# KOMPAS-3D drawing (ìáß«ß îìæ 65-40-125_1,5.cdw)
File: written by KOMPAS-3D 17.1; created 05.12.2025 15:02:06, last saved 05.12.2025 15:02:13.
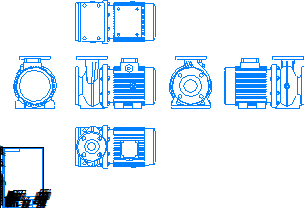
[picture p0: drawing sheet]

Sheet 1: A4, portrait

Title block, sheet 1: name: Насос МНС / 65-40-125_1,5; material: Сталь 10  ГОСТ 1050-88; mass: 75,87; sheets: 1; sheet format: A4

Views: Проекционный вид 2, Проекционный вид 3, Проекционный вид 4, Проекционный вид 5, Проекционный вид 6
Referenced files in \\adlc.lan\data\АДЛ_ПКД\3D-модели\ADL production\Насосы ГРАНПАМП\Насосы ГРАНПАМП серии МНС\KOMPAS 3D\: Насос МНС 65-40-125_1,5.m3d
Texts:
  Andrey
  АДЛ
Dimensions and other numbers on the sheet: 1:1; 1; 65-40-125_1,5; 75,87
